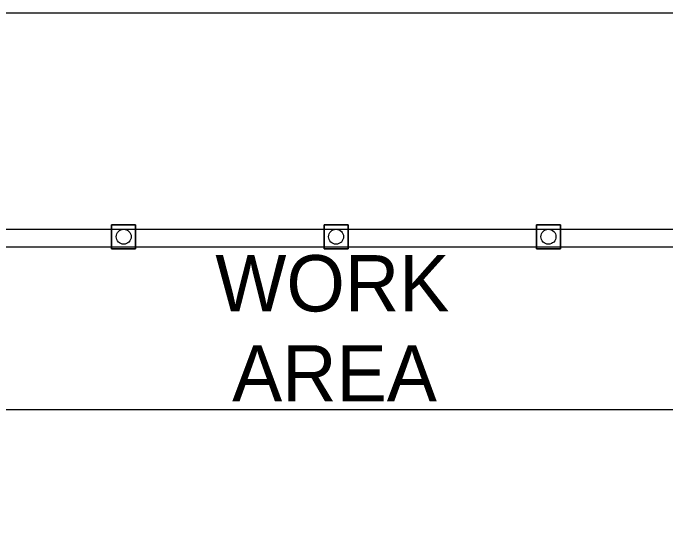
# Model space of a CAD drawing. Extents: x 99999.1 to 100055.7, y 99995 to 100013.2.
# Drawn here: x 100031.905 to 100033.065, y 100006.564 to 100007.468 of the extents above; entities that cross this region are included whole.
import ezdxf

# ---------------------------------------------------------------- set-up
doc = ezdxf.new("R2010")
doc.units = 0
for name, color, linetype in [('RD_MK_LineEdgeYellow', 7, 'Continuous'), ('RD_MK_LineLane', 7, 'Continuous'), ('TR_WZ_TrafficCone', 7, 'Continuous'), ('TR_WZ_WorkAreaLabel', 7, 'Continuous'), ('TR_WZ_WorkZoneDetails', 7, 'Continuous')]:
    doc.layers.add(name, color=color, linetype=linetype)

msp = doc.modelspace()

# ---------------------------------------------------------------- linework, layer by layer
at = {"layer": 'RD_MK_LineEdgeYellow'}
msp.add_line((100031.7238, 100007.084), (100033.2341, 100007.084), dxfattribs=at)
at = {"layer": 'RD_MK_LineLane'}
msp.add_lwpolyline([(100033.2341, 100007.468), (100031.6607, 100007.468)], dxfattribs=at)
at = {"layer": 'TR_WZ_TrafficCone'}
for points in [[(100032.08, 100007.092), (100032.1227, 100007.092), (100032.1227, 100007.0493), (100032.08, 100007.0493), (100032.08, 100007.092)], [(100032.08, 100007.0493), (100032.1227, 100007.0493), (100032.1227, 100007.092), (100032.08, 100007.092), (100032.08, 100007.0493)], [(100032.4576, 100007.092), (100032.5003, 100007.092), (100032.5003, 100007.0493), (100032.4576, 100007.0493), (100032.4576, 100007.092)], [(100032.4576, 100007.0493), (100032.5003, 100007.0493), (100032.5003, 100007.092), (100032.4576, 100007.092), (100032.4576, 100007.0493)], [(100032.8352, 100007.092), (100032.8779, 100007.092), (100032.8779, 100007.0493), (100032.8352, 100007.0493), (100032.8352, 100007.092)], [(100032.8352, 100007.0493), (100032.8779, 100007.0493), (100032.8779, 100007.092), (100032.8352, 100007.092), (100032.8352, 100007.0493)]]:
    msp.add_lwpolyline(points, dxfattribs=at)
for centre in [(100032.1014, 100007.0707), (100032.4789, 100007.0707), (100032.8565, 100007.0707)]:
    msp.add_circle(centre, 0.0133, dxfattribs=at)
at = {"layer": 'TR_WZ_WorkZoneDetails'}
msp.add_line((100031.7105, 100006.764), (100033.2341, 100006.764), dxfattribs=at)
msp.add_lwpolyline([(100033.7873, 100007.436), (100033.2263, 100007.052), (100031.7283, 100007.052), (100031.0359, 100006.8182), (100031.0359, 100006.8182), (100031.0359, 100006.8182), (100031.1223, 100006.564), (100031.1223, 100006.564), (100031.1223, 100006.564), (100031.7105, 100006.764), (100033.2341, 100006.764), (100033.5146, 100006.956), (100033.7951, 100007.148), (100035.35, 100007.148), (100035.35, 100007.436)], close=True, dxfattribs=at)

# ---------------------------------------------------------------- texts
at = {"layer": 'TR_WZ_WorkAreaLabel'}
for s, p in [('WORK', (100032.2644, 100006.938)), ('AREA', (100032.2941, 100006.778))]:
    msp.add_text(s, height=0.1, dxfattribs=at).set_placement(p)

doc.saveas('drawing.dxf')
